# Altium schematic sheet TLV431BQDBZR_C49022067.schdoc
size 127 x 101 mm
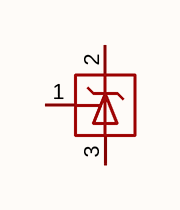
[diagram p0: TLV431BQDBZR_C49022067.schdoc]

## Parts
U?  tlv431bqdbzr_c49022067  [SOT-23-3_L3.0-W1.7-P0.95-LS2.9-BR]  (value not drawn)

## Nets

Not connected (* = marked no-connect by the designer): U? 1(REF) 2(C) 3(A)

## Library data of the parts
U? = tlv431bqdbzr_c49022067: 输出极性:正极;工作电压:18V;输出电压:1.24V~18V;输出电流:100mA;电源纹波抑制比(PSRR):-;输出类型:可调;; Manufacturer: JSMSEMI(杰盛微); AddInBom: yes; ModelId: 89cb27a44ab2466697082bb9fd73a7d0; ModelName: SOT-23-3L_L2.9-W1.6-H1.1-LS2.8-P0.95; ModelTransform: 114.173,110.236,0,90,0,0,0,0,0; Output Configuration: 正极; Voltage - Supply: 18V; Output Current: 100mA; Output Type: 可调; Number of Outputs: 1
